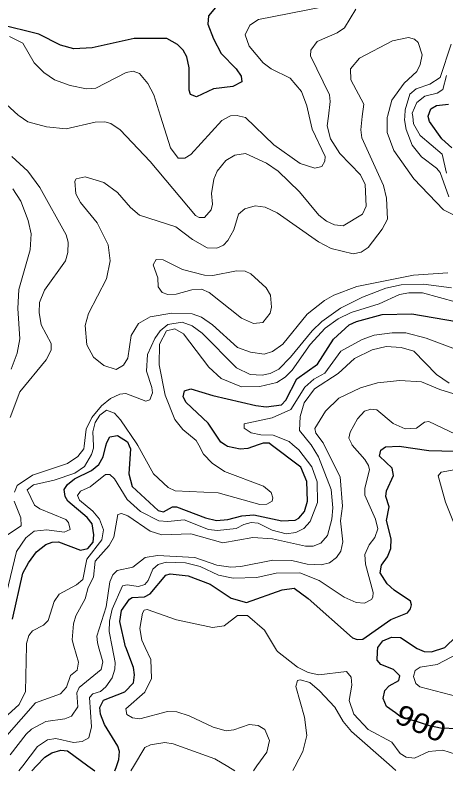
# Model space of a CAD drawing. Extents: x 473.9 to 500, y 7733.1 to 7760.8.
# Drawn here: x 480.782 to 482.505, y 7733.144 to 7736.165 of the extents above; entities that cross this region are included whole.
import ezdxf
from ezdxf.enums import TextEntityAlignment as Align

# ---------------------------------------------------------------- set-up
doc = ezdxf.new("R2010")
doc.units = 0
doc.header["$LTSCALE"] = 0.032
doc.layers.add('1', color=7, linetype='Continuous', lineweight=25)
doc.layers.add('2', color=7, linetype='Continuous', lineweight=13)
doc.layers.add('61', color=7, linetype='Continuous')

msp = doc.modelspace()

# ---------------------------------------------------------------- linework, layer by layer
at = {"layer": '1'}
for points in [[(481.6029, 7736.2198), (481.5553, 7736.162), (481.5527, 7736.1297), (481.575, 7736.0702), (481.6062, 7736.0123), (481.6667, 7735.9505), (481.6856, 7735.9211), (481.6889, 7735.8989), (481.6533, 7735.8796), (481.5759, 7735.871), (481.5079, 7735.8385), (481.4833, 7735.8476), (481.4784, 7735.8655), (481.4782, 7735.9546), (481.4689, 7735.9979), (481.4541, 7736.0256), (481.4315, 7736.0475), (481.3886, 7736.0724), (481.2577, 7736.0715), (481.0904, 7736.0339), (481.0162, 7736.0306), (480.964, 7736.0445), (480.8766, 7736.0886), (480.7135, 7736.1292)], [(482.5283, 7735.6352), (482.4886, 7735.6708), (482.439, 7735.74), (482.434, 7735.7601), (482.4336, 7735.7616), (482.4441, 7735.7907), (482.468, 7735.8037), (482.5154, 7735.8087)], [(481.2436, 7734.4308), (481.2363, 7734.3314), (481.2497, 7734.281), (481.3535, 7734.1851), (481.3758, 7734.1798), (481.412, 7734.1999), (481.4274, 7734.1995), (481.5438, 7734.155), (481.5876, 7734.1443), (481.6323, 7734.1487), (481.6894, 7734.1639), (481.7374, 7734.1674), (481.8484, 7734.1436), (481.9027, 7734.1463), (481.9172, 7734.1545), (481.9392, 7734.1804), (481.951, 7734.2214), (481.9493, 7734.3008), (481.925, 7734.3584), (481.8065, 7734.4474), (481.7983, 7734.4535), (481.7738, 7734.4535), (481.7543, 7734.447), (481.7121, 7734.433), (481.6819, 7734.4297), (481.6319, 7734.4412), (481.6236, 7734.4462), (481.6045, 7734.4577), (481.5546, 7734.5334), (481.4655, 7734.6159), (481.4543, 7734.6398), (481.4593, 7734.6627), (481.4851, 7734.6714), (481.5726, 7734.6445), (481.7442, 7734.6041), (481.7864, 7734.5994), (481.8469, 7734.6078), (481.865, 7734.6259), (481.9091, 7734.7117), (481.9908, 7734.7695), (482.0548, 7734.8702), (482.1179, 7734.9269), (482.1473, 7734.941), (482.2501, 7734.9683), (482.3688, 7734.9715), (482.5934, 7734.9323)], [(480.7715, 7733.7502), (480.8128, 7733.9342), (480.8351, 7733.9759), (480.8681, 7734.0196), (480.9053, 7734.049), (480.9298, 7734.0579), (480.9553, 7734.0588), (481.0433, 7734.0268), (481.0729, 7734.0334), (481.0939, 7734.0575), (481.0971, 7734.0876), (481.09, 7734.1308), (481.0706, 7734.157), (480.9925, 7734.222), (480.9815, 7734.2407), (480.9783, 7734.2683), (480.9918, 7734.2887), (481.0196, 7734.3118), (481.088, 7734.3446), (481.1162, 7734.3686), (481.1341, 7734.3995), (481.1448, 7734.4432), (481.1482, 7734.4568), (481.1613, 7734.4789), (481.1917, 7734.484), (481.2314, 7734.4595), (481.2381, 7734.4438), (481.2436, 7734.4308)], [(481.1814, 7733.144), (481.186, 7733.1575), (481.1969, 7733.1893), (481.1992, 7733.2212), (481.1934, 7733.243), (481.1393, 7733.3286), (481.1231, 7733.3703), (481.1204, 7733.3977), (481.1354, 7733.4262), (481.2207, 7733.4594), (481.2556, 7733.4962), (481.2595, 7733.528), (481.2555, 7733.5573), (481.2243, 7733.6381), (481.2239, 7733.639), (481.2002, 7733.7406), (481.2076, 7733.7846), (481.2389, 7733.8305), (481.2499, 7733.8363), (481.2989, 7733.8393), (481.3227, 7733.851), (481.3848, 7733.9265), (481.4018, 7733.9319), (481.4739, 7733.9236), (481.5617, 7733.8896), (481.6467, 7733.8341), (481.707, 7733.8164), (481.8503, 7733.867), (481.8987, 7733.874), (481.9547, 7733.8335), (482.1318, 7733.6761), (482.1498, 7733.6693), (482.1721, 7733.6701), (482.2842, 7733.7491), (482.3513, 7733.7756), (482.3637, 7733.7911), (482.3675, 7733.807), (482.3633, 7733.8223), (482.2974, 7733.8657), (482.2702, 7733.8917), (482.2422, 7733.9355), (482.248, 7733.9657), (482.2718, 7733.9995), (482.2844, 7734.0323), (482.2855, 7734.0713), (482.268, 7734.1442), (482.2774, 7734.1992), (482.2648, 7734.2404), (482.2679, 7734.2632), (482.2952, 7734.3252), (482.2903, 7734.3536), (482.2393, 7734.4017), (482.2451, 7734.4261), (482.2639, 7734.4392), (482.318, 7734.4418), (482.4367, 7734.4249), (482.695, 7734.4176)], [(482.5508, 7733.3114), (482.484, 7733.3145), (482.4395, 7733.3239), (482.3877, 7733.3415), (482.3275, 7733.3578), (482.3036, 7733.3755), (482.268, 7733.4005), (482.2536, 7733.4335), (482.2608, 7733.4653), (482.2776, 7733.4831), (482.3163, 7733.5044), (482.3207, 7733.5243), (482.2951, 7733.5491), (482.2451, 7733.5684), (482.2302, 7733.586), (482.2315, 7733.6191), (482.2323, 7733.6376), (482.2532, 7733.6637), (482.2878, 7733.678), (482.3235, 7733.6774), (482.3896, 7733.6325), (482.4181, 7733.6216), (482.4479, 7733.6201), (482.5001, 7733.6374), (482.5464, 7733.6809)], [(480.8489, 7733.1438), (480.8679, 7733.1636), (480.9014, 7733.1985), (480.9283, 7733.2164), (480.9654, 7733.2261), (480.991, 7733.2235), (481.0724, 7733.1642), (481.1002, 7733.144)]]:
    msp.add_lwpolyline(points, dxfattribs=at)
at = {"layer": '2'}
for points in [[(482.0068, 7736.1976), (481.756, 7736.1476), (481.7201, 7736.1254), (481.702, 7736.086), (481.7178, 7736.0416), (481.7737, 7735.9747), (481.8058, 7735.9504), (481.8815, 7735.9138), (481.9277, 7735.86), (481.9486, 7735.8021), (481.9581, 7735.7608), (481.9698, 7735.7099), (482.0214, 7735.5995), (482.0208, 7735.5813), (482.0084, 7735.5594), (481.9803, 7735.5537), (481.9226, 7735.5719), (481.8169, 7735.6462), (481.7032, 7735.7554), (481.6798, 7735.7612), (481.6707, 7735.7635), (481.6439, 7735.7626), (481.6414, 7735.7613), (481.6094, 7735.7444), (481.4853, 7735.6079), (481.4603, 7735.593), (481.4337, 7735.5932), (481.4038, 7735.6348), (481.3638, 7735.7617), (481.3373, 7735.8461), (481.3129, 7735.8915), (481.2801, 7735.932), (481.2541, 7735.941), (481.2259, 7735.9364), (481.1047, 7735.8736), (481.0677, 7735.8709), (481.0018, 7735.8839), (480.9401, 7735.9071), (480.8974, 7735.9355), (480.8582, 7735.9747), (480.8124, 7736.0529), (480.7595, 7736.0799)], [(481.9899, 7736.0592), (482.0694, 7736.0945), (482.0994, 7736.1145), (482.1453, 7736.1891)], [(480.7129, 7735.8383), (480.7935, 7735.7656), (480.7979, 7735.7626), (480.8324, 7735.7393), (480.9068, 7735.7187), (480.9866, 7735.7105), (481.1017, 7735.7379), (481.1403, 7735.7385), (481.1647, 7735.7321), (481.2017, 7735.7072), (481.3223, 7735.5802), (481.5032, 7735.3648), (481.5179, 7735.3566), (481.5396, 7735.3564), (481.5655, 7735.3863), (481.5708, 7735.4088), (481.5668, 7735.452), (481.5766, 7735.5099), (481.5899, 7735.5417), (481.6242, 7735.5838), (481.661, 7735.6048), (481.7029, 7735.6115), (481.7874, 7735.5736), (481.8339, 7735.5416), (481.9189, 7735.4588), (481.9973, 7735.3652), (482.0276, 7735.3409), (482.0599, 7735.3267), (482.0936, 7735.3234), (482.1717, 7735.37), (482.1866, 7735.4017), (482.1818, 7735.4887), (482.1633, 7735.5271), (482.0803, 7735.6123), (482.0438, 7735.6702), (482.0299, 7735.7223), (482.035, 7735.7607), (482.0427, 7735.8193), (482.0396, 7735.8466), (481.9631, 7736.0021), (481.9648, 7736.0256), (481.9899, 7736.0592)], [(482.5129, 7735.1345), (482.3758, 7735.1251), (482.1483, 7735.0799), (482.0572, 7735.0463), (482.0195, 7735.0248), (481.9499, 7734.9703), (481.8525, 7734.8498), (481.8111, 7734.8205), (481.778, 7734.8098), (481.7238, 7734.8178), (481.6719, 7734.8364), (481.5715, 7734.9265), (481.5275, 7734.9581), (481.4895, 7734.9709), (481.4091, 7734.9739), (481.3218, 7734.9593), (481.2754, 7734.9317), (481.246, 7734.8839), (481.2328, 7734.7932), (481.2151, 7734.7655), (481.1855, 7734.7484), (481.1368, 7734.7644), (481.0953, 7734.7984), (481.0684, 7734.847), (481.0622, 7734.9247), (481.0756, 7734.9724), (481.1469, 7735.1106), (481.1622, 7735.1832), (481.1543, 7735.2473), (481.1107, 7735.3349), (481.0436, 7735.4164), (481.0253, 7735.451), (481.021, 7735.5009), (481.0263, 7735.5101), (481.062, 7735.5181), (481.1374, 7735.4958), (481.1919, 7735.4564), (481.2435, 7735.3963), (481.279, 7735.3656), (481.425, 7735.319), (481.4919, 7735.2681), (481.5501, 7735.2343), (481.5882, 7735.2336), (481.6157, 7735.2461), (481.6331, 7735.2638), (481.6574, 7735.3063), (481.6756, 7735.3696), (481.7002, 7735.3911), (481.7418, 7735.4034), (481.7822, 7735.3969), (481.8304, 7735.3752), (481.9956, 7735.259), (482.0454, 7735.2325), (482.1339, 7735.2112), (482.1659, 7735.2173), (482.1935, 7735.2358), (482.2498, 7735.3095), (482.2708, 7735.3497), (482.2668, 7735.4333), (482.255, 7735.4837), (482.1687, 7735.6746), (482.1642, 7735.7067), (482.1705, 7735.7605), (482.1762, 7735.8088), (482.1248, 7735.9066), (482.1239, 7735.9508), (482.1593, 7735.9933), (482.291, 7736.0629), (482.3553, 7736.0763), (482.3799, 7736.0692), (482.3942, 7736.0563), (482.4101, 7736.0063), (482.4026, 7735.9677), (482.3883, 7735.9405), (482.3379, 7735.8928), (482.2891, 7735.8252), (482.271, 7735.7603), (482.2703, 7735.7577), (482.2704, 7735.6965), (482.2971, 7735.6246), (482.3764, 7735.5105), (482.4956, 7735.3869), (482.5818, 7735.3444)], [(482.5267, 7736.0497), (482.4821, 7735.916), (482.4408, 7735.8886), (482.3864, 7735.8712), (482.3607, 7735.849), (482.3424, 7735.7864), (482.3405, 7735.7602), (482.3395, 7735.7471), (482.3456, 7735.7085), (482.3706, 7735.645), (482.407, 7735.5986), (482.4677, 7735.5536), (482.4821, 7735.536), (482.5171, 7735.4384)], [(482.507, 7735.5331), (482.4894, 7735.6096), (482.4018, 7735.6842), (482.3754, 7735.7308), (482.3721, 7735.7602), (482.3706, 7735.7738), (482.3892, 7735.8156), (482.4204, 7735.841), (482.4694, 7735.8532), (482.4922, 7735.8681), (482.5074, 7735.9236)], [(480.7622, 7734.5565), (480.8009, 7734.6594), (480.906, 7734.7876), (480.9257, 7734.8253), (480.9255, 7734.8519), (480.8865, 7734.9264), (480.8778, 7734.9766), (480.8794, 7735.0158), (480.8999, 7735.0651), (480.9834, 7735.1825), (480.9923, 7735.2163), (480.9935, 7735.258), (480.9861, 7735.2862), (480.8809, 7735.4757), (480.8333, 7735.541), (480.7691, 7735.6003)], [(480.7732, 7735.4709), (480.8054, 7735.422), (480.8343, 7735.3444), (480.8463, 7735.2907), (480.8423, 7735.2265), (480.7974, 7735.0678), (480.7933, 7734.9927), (480.8005, 7734.871), (480.79, 7734.8133), (480.7664, 7734.7499)], [(482.5277, 7735.0754), (482.4152, 7735.0897), (482.3263, 7735.0866), (482.265, 7735.074), (482.1719, 7735.0378), (482.084, 7734.9938), (482.0084, 7734.9402), (481.97, 7734.9037), (481.8839, 7734.7976), (481.8368, 7734.7503), (481.8025, 7734.7326), (481.7695, 7734.7257), (481.7222, 7734.7281), (481.6676, 7734.7557), (481.5297, 7734.8936), (481.4895, 7734.9225), (481.4503, 7734.9378), (481.3931, 7734.9279), (481.3619, 7734.9026), (481.3406, 7734.873), (481.3113, 7734.8079), (481.3071, 7734.7424), (481.3294, 7734.677), (481.331, 7734.6552), (481.3213, 7734.6274), (481.3043, 7734.6213), (481.2252, 7734.6523), (481.2007, 7734.65), (481.1636, 7734.6326), (481.1268, 7734.6031), (481.0882, 7734.5565), (481.0664, 7734.5096), (481.0583, 7734.4426), (481.0569, 7734.4309), (481.0331, 7734.4006), (480.9909, 7734.3727), (480.8518, 7734.3262), (480.7906, 7734.2853), (480.7795, 7734.2578)], [(480.7479, 7733.8543), (480.7879, 7734.0208), (480.825, 7734.0756), (480.8585, 7734.1018), (480.9091, 7734.1073), (480.9779, 7734.0976), (481.0018, 7734.1088), (480.9956, 7734.1367), (480.9849, 7734.1489), (480.8807, 7734.1915), (480.86, 7734.2059), (480.8306, 7734.2673), (480.8558, 7734.287), (480.9386, 7734.3064), (481.0205, 7734.3343), (481.059, 7734.3601), (481.0881, 7734.409), (481.0956, 7734.4338), (481.0953, 7734.4429), (481.0932, 7734.4992), (481.1023, 7734.5372), (481.1206, 7734.5655), (481.1476, 7734.5856), (481.1792, 7734.5734), (481.2037, 7734.5474), (481.269, 7734.4512), (481.273, 7734.444), (481.335, 7734.3316), (481.3942, 7734.2764), (481.4215, 7734.2629), (481.5936, 7734.2553), (481.7613, 7734.2086), (481.7881, 7734.2105), (481.8106, 7734.2227), (481.8133, 7734.2349), (481.8063, 7734.2572), (481.775, 7734.2825), (481.6188, 7734.3409), (481.5699, 7734.3738), (481.536, 7734.4104), (481.5166, 7734.4455), (481.506, 7734.4646), (481.4531, 7734.508), (481.4205, 7734.5479), (481.3824, 7734.6454), (481.3582, 7734.7676), (481.3598, 7734.8501), (481.3876, 7734.9037), (481.4203, 7734.9106), (481.4556, 7734.8915), (481.5567, 7734.7578), (481.6064, 7734.7121), (481.6876, 7734.6795), (481.7608, 7734.6807), (481.8294, 7734.6971), (481.8627, 7734.7173), (481.8903, 7734.7461), (481.9623, 7734.849), (482.0223, 7734.9132), (482.0734, 7734.9506), (482.1259, 7734.9762), (482.2379, 7735.0114), (482.3194, 7735.0479), (482.3565, 7735.0554), (482.4115, 7735.0551), (482.5473, 7735.0178)], [(482.575, 7734.8181), (482.426, 7734.8738), (482.345, 7734.8946), (482.2898, 7734.8952), (482.2186, 7734.8862), (482.1697, 7734.8686), (482.085, 7734.8216), (482.0211, 7734.7336), (481.9766, 7734.7101), (481.9404, 7734.6782), (481.8842, 7734.5885), (481.8101, 7734.5546), (481.6982, 7734.5307), (481.698, 7734.5144), (481.7261, 7734.4957), (481.7645, 7734.4868), (481.8144, 7734.4863), (481.8777, 7734.4601), (481.8924, 7734.4479), (481.9173, 7734.4272), (481.969, 7734.359), (481.9896, 7734.2997), (481.992, 7734.2171), (481.962, 7734.1403), (481.9368, 7734.1123), (481.9049, 7734.097), (481.8658, 7734.092), (481.8097, 7734.1061), (481.7538, 7734.1336), (481.7266, 7734.1369), (481.6964, 7734.1293), (481.6666, 7734.1121), (481.5908, 7734.1049), (481.5558, 7734.1094), (481.4581, 7734.1468), (481.3924, 7734.1402), (481.3566, 7734.1434), (481.283, 7734.1807), (481.2304, 7734.2292), (481.1788, 7734.3119), (481.1613, 7734.3284), (481.1439, 7734.328), (481.0819, 7734.2787), (481.0434, 7734.2622), (481.0321, 7734.245), (481.0392, 7734.2265), (481.0931, 7734.1821), (481.1197, 7734.1505), (481.1348, 7734.1068), (481.1286, 7734.0671), (481.0683, 7733.9895), (481.0524, 7733.9092), (481.0279, 7733.8875), (480.9578, 7733.8503), (480.9386, 7733.8204), (480.9144, 7733.7452), (480.896, 7733.7261), (480.8511, 7733.7039), (480.8362, 7733.6846), (480.8271, 7733.6533), (480.8269, 7733.6456), (480.8231, 7733.4614), (480.7977, 7733.4089), (480.7533, 7733.3681)], [(482.0735, 7734.7325), (482.1393, 7734.7922), (482.2094, 7734.8276), (482.2662, 7734.8404), (482.3257, 7734.8365), (482.3766, 7734.8221), (482.4669, 7734.7284), (482.5177, 7734.6932)], [(480.749, 7733.2856), (480.863, 7733.4163), (480.9634, 7733.4522), (480.987, 7733.4784), (481.0037, 7733.5246), (481.0295, 7733.5458), (481.0353, 7733.5777), (481.0174, 7733.642), (481.0104, 7733.6672), (481.0159, 7733.7321), (481.0254, 7733.7642), (481.0621, 7733.8316), (481.0737, 7733.8768), (481.0956, 7733.9176), (481.1018, 7733.9815), (481.1587, 7734.0446), (481.1768, 7734.0784), (481.1923, 7734.1686), (481.2071, 7734.1723), (481.2334, 7734.1637), (481.3222, 7734.1019), (481.3684, 7734.087), (481.4847, 7734.0911), (481.6124, 7734.0559), (481.7325, 7734.0774), (481.8108, 7734.0713), (481.9435, 7734.0415), (481.9747, 7734.0418), (482.0049, 7734.0535), (482.0315, 7734.0852), (482.0482, 7734.1506), (482.0523, 7734.1957), (482.0467, 7734.269), (481.9953, 7734.3999), (481.9662, 7734.4472), (481.9652, 7734.4484), (481.919, 7734.5044), (481.9219, 7734.5611), (481.9383, 7734.615), (481.9789, 7734.6712), (482.0735, 7734.7325)], [(482.5932, 7734.6335), (482.4802, 7734.6686), (482.4072, 7734.699), (482.3207, 7734.7039), (482.2314, 7734.6951), (482.1628, 7734.6754), (482.077, 7734.6334), (482.0237, 7734.5816), (481.9802, 7734.5123), (481.9844, 7734.4941), (482.0138, 7734.4554), (482.0172, 7734.4487), (482.0824, 7734.319), (482.0909, 7734.2016), (482.083, 7734.1431), (482.0933, 7734.0601), (482.0846, 7734.0225), (482.0676, 7733.9964), (482.0389, 7733.9759), (482.0057, 7733.9674), (481.9502, 7733.9703), (481.8894, 7733.9843), (481.8123, 7733.9866), (481.6841, 7733.9603), (481.6444, 7733.9578), (481.5893, 7733.9661), (481.5008, 7733.9963), (481.3515, 7734.0043), (481.3025, 7733.9969), (481.2526, 7733.9584), (481.1899, 7733.9453), (481.1724, 7733.9276), (481.1611, 7733.8993), (481.1457, 7733.7994), (481.1093, 7733.6827), (481.1108, 7733.6576), (481.1159, 7733.6401), (481.1334, 7733.5798), (481.1258, 7733.5489), (481.0378, 7733.4777), (481.0289, 7733.4561), (481.0333, 7733.4002), (481.0074, 7733.3624), (480.9813, 7733.3519), (480.9053, 7733.3408), (480.8475, 7733.3109), (480.8256, 7733.291), (480.7627, 7733.2074)], [(480.7974, 7733.1437), (480.8123, 7733.1633), (480.8713, 7733.2406), (480.9116, 7733.2679), (480.9445, 7733.2736), (481.0153, 7733.2575), (481.0506, 7733.2615), (481.0764, 7733.276), (481.0876, 7733.3194), (481.0796, 7733.4368), (481.0932, 7733.4521), (481.1238, 7733.4609), (481.1447, 7733.4794), (481.1704, 7733.5156), (481.1809, 7733.551), (481.1817, 7733.5767), (481.17, 7733.6391), (481.1584, 7733.7005), (481.1592, 7733.7423), (481.1704, 7733.7906), (481.2114, 7733.8838), (481.2307, 7733.8878), (481.2758, 7733.8814), (481.3007, 7733.8886), (481.3144, 7733.9055), (481.3328, 7733.9497), (481.3546, 7733.9682), (481.3867, 7733.9779), (481.4639, 7733.9755), (481.5218, 7733.961), (481.5958, 7733.9256), (481.6537, 7733.9136), (481.7485, 7733.9168), (481.8257, 7733.9337), (481.9206, 7733.9361), (481.9978, 7733.9047), (482.0975, 7733.8388), (482.1457, 7733.8171), (482.1795, 7733.8147), (482.2068, 7733.8291), (482.2132, 7733.838), (482.214, 7733.8565), (482.1835, 7733.9707), (482.1803, 7734.0092), (482.198, 7734.0478), (482.2213, 7734.0768), (482.2325, 7734.1113), (482.2229, 7734.1507), (482.1803, 7734.2456), (482.1811, 7734.2746), (482.1996, 7734.3469), (482.1948, 7734.3646), (482.1811, 7734.3887), (482.1296, 7734.4466), (482.1283, 7734.4494), (482.1168, 7734.474), (482.1216, 7734.4981), (482.1513, 7734.5511), (482.1795, 7734.5817), (482.2052, 7734.5897), (482.2293, 7734.5873), (482.2944, 7734.5319), (482.3419, 7734.5117), (482.3869, 7734.5142), (482.4199, 7734.5375), (482.4368, 7734.5407), (482.5429, 7734.49)], [(482.628, 7734.3628), (482.4862, 7734.3375), (482.4734, 7734.3229), (482.5028, 7734.2183), (482.5516, 7734.0987)], [(480.7779, 7734.2218), (480.8054, 7734.1549), (480.8063, 7734.1236), (480.7357, 7734.0771)], [(482.5435, 7733.2111), (482.493, 7733.226), (482.437, 7733.2212), (482.3793, 7733.1949), (482.3467, 7733.198), (482.3222, 7733.2138), (482.2887, 7733.2581), (482.1936, 7733.3094), (482.1371, 7733.3698), (482.1177, 7733.4249), (482.1287, 7733.487), (482.1264, 7733.5182), (482.1077, 7733.5405), (481.9966, 7733.5276), (481.9544, 7733.5375), (481.9112, 7733.5589), (481.8317, 7733.6205), (481.828, 7733.6267), (481.7798, 7733.7068), (481.7118, 7733.7644), (481.6708, 7733.7645), (481.6175, 7733.7242), (481.5711, 7733.7166), (481.4273, 7733.7477), (481.3104, 7733.7889), (481.2985, 7733.7862), (481.291, 7733.774), (481.2806, 7733.7133), (481.2882, 7733.6668), (481.3024, 7733.6366), (481.3247, 7733.5894), (481.3273, 7733.5133), (481.3003, 7733.4588), (481.2254, 7733.3912), (481.2288, 7733.3691), (481.2509, 7733.3555), (481.2804, 7733.3516), (481.3908, 7733.3806), (481.4284, 7733.3804), (481.4779, 7733.3637), (481.5743, 7733.318), (481.6257, 7733.3033), (481.657, 7733.3076), (481.7184, 7733.329), (481.7546, 7733.3251), (481.781, 7733.3096), (481.7992, 7733.2653), (481.7888, 7733.2185), (481.7493, 7733.1642), (481.7349, 7733.1445)], [(482.305, 7733.1449), (482.278, 7733.1687), (482.1278, 7733.301), (482.0937, 7733.3413), (482.0612, 7733.3981), (481.999, 7733.4644), (481.9602, 7733.4964), (481.9222, 7733.5074), (481.9112, 7733.5047), (481.9054, 7733.4812), (481.939, 7733.3579), (481.9486, 7733.2855), (481.9322, 7733.2208), (481.9005, 7733.1594), (481.8928, 7733.1446)], [(481.6611, 7733.1444), (481.6322, 7733.1614), (481.5801, 7733.192), (481.414, 7733.2518), (481.3809, 7733.2573), (481.323, 7733.2474), (481.301, 7733.2366), (481.2549, 7733.161), (481.2446, 7733.1441)]]:
    msp.add_lwpolyline(points, dxfattribs=at)
for points in [[(481.7863, 7735.0749), (481.7243, 7735.1309), (481.7021, 7735.1412), (481.668, 7735.1428), (481.5721, 7735.1245), (481.5399, 7735.126), (481.4512, 7735.1486), (481.3738, 7735.187), (481.3457, 7735.1876), (481.3338, 7735.1674), (481.353, 7735.115), (481.354, 7735.0796), (481.3697, 7735.0564), (481.3931, 7735.048), (481.4257, 7735.0496), (481.4884, 7735.0672), (481.5275, 7735.0701), (481.5583, 7735.0563), (481.6874, 7734.9532), (481.735, 7734.9322), (481.7726, 7734.9363), (481.8025, 7734.9738), (481.8072, 7734.9972), (481.8031, 7735.0463)], [(482.7699, 7733.518), (482.7879, 7733.5277), (482.8034, 7733.5472), (482.8025, 7733.5879), (482.7797, 7733.6088), (482.7711, 7733.6167), (482.7025, 7733.6297), (482.6186, 7733.6132), (482.5573, 7733.6144), (482.5546, 7733.613), (482.4701, 7733.5695), (482.4025, 7733.5586), (482.3826, 7733.5456), (482.3748, 7733.5217), (482.3842, 7733.4935), (482.4006, 7733.4802), (482.5542, 7733.4399), (482.5943, 7733.4448), (482.6239, 7733.4565), (482.6933, 7733.505)]]:
    msp.add_lwpolyline(points, close=True, dxfattribs=at)

# ---------------------------------------------------------------- texts
at = {"layer": '61', "width": 1.15}
msp.add_text('900', height=0.08, rotation=335.225, dxfattribs=at).set_placement((482.3877, 7733.2975), align=Align.CENTER)

doc.saveas('drawing.dxf')
